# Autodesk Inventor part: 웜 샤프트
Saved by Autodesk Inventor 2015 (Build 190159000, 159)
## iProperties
Created: 2025-06
Part Number: 웜 샤프트
Material: 일반
Document SubType Name: Modeling
Designer: User
Density: 1 g/cm^3
Appearance: 기본값
Author: User
Author: jhkim
Creation Date: 2025-05-23
Sending System: Autodesk Inventor 2026
Preprocessor: ST-DEVELOPER v20.1
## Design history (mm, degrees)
node "웜 샤프트1"
body "Solid1"
node "기준1"
